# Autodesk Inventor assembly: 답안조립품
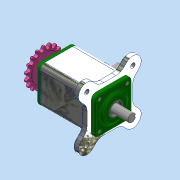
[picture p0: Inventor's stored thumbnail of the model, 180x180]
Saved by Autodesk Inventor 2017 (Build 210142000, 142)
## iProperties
Part Number: 답안조립품
Material: 일반
Document SubType Name: Assembly
Designer: MRC
Author: MRC
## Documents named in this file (11)
- C:\Users\MRC\Desktop\711109V1001\답안조립품.iam
- C:\Users\MRC\Desktop\711109V1001\본체.ipt
- C:\Users\MRC\Desktop\711109V1001\베어링 6203.ipt
- C:\Users\MRC\Desktop\711109V1001\볼트 M4.ipt
- C:\Users\MRC\Desktop\711109V1001\부시.ipt
- C:\Users\MRC\Desktop\711109V1001\스프로킷.ipt
- C:\Users\MRC\Desktop\711109V1001\슬라이더.ipt
- C:\Users\MRC\Desktop\711109V1001\오일 실.ipt
- C:\Users\MRC\Desktop\711109V1001\커버.ipt
- C:\Users\MRC\Desktop\711109V1001\키 4 x 4 x 14.ipt
- C:\Users\MRC\Desktop\711109V1001\편심축.ipt
